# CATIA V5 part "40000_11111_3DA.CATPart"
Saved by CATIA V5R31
Part number: 40000_11111_3DA
Bounding box of the stored display mesh (mm): x 126.565 to 340.614, y 897.639 to 1023.2, z 1313.857 to 1558.404
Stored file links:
  \\solize.local\damia\dept\DDE_Design\10_order\2305701_JAMA_変換検証STEP3_お手本モデル作成\work\04_ダイハツ_鋳造\10_CATIA_V5\231219_案bCATIAデータ\40000_11111_3DA.CATPart
  D:\CATIA\DS\main\win_b64\resources\graphic\CATTPSGeneralTolerance.xlsx
  G:\BODY\BX\_K_PROJECT\610_3D単独図\02_検討\79_自工会提出3D図面データ（ナックル改）\01_CATIA_DATA\PROPERTY.xls
  G:\BODY\BX\_K_PROJECT\610_3D単独図\02_検討\79_自工会提出3D図面データ（ナックル改）\01_CATIA_DATA\3DM_230830\PROPERTY.xls
  G:\BODY\BX\_K_PROJECT\610_3D単独図\02_検討\79_自工会提出3D図面データ（ナックル改）\01_CATIA_DATA\PROPERTY_3DA.xls
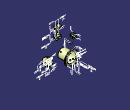
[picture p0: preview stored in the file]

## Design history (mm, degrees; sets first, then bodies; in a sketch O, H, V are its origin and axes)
TTRSSet1
f4a2d38f3ddc11d3a929006094b99c4b_11 "CATTPSSet"
Set1 "幾何公差要素"
  DatumSurface1 to DatumSurface4
  Point1: stored without definition
  Point2: stored without definition
  Line1: stored without definition
  Point3: stored without definition
  Point4: stored without definition
  Plane1: stored without definition
  Point5: stored without definition
Set2 "表面性状用要素（幾何公差要素）"
  Set3 "Ra1.6"
    DatumSurface5
    DatumSurface6
    DatumCurve1
  Set4 "Ra6.3"
    DatumSurface7 to DatumSurface17
  Set5 "Ra25"
    DatumSurface18 to DatumSurface22
Set6 "断面"
  Set7 "A-A"
    DatumCurve2
Set8 "識別マーク"
  DatumCurve3
Body1 (main body)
